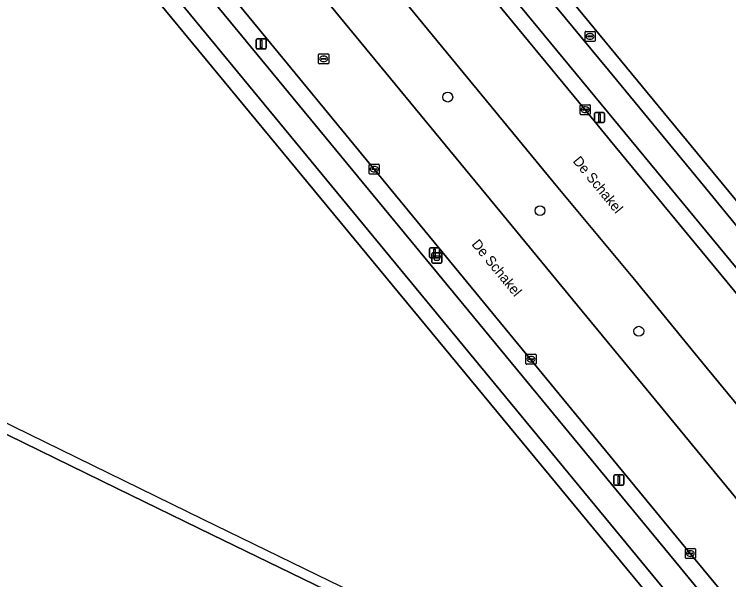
# Model space of a CAD drawing. Extents: x 156141 to 158132, y 385651 to 388333.
# Drawn here: x 156871.2 to 156942.3, y 386572.8 to 386629.1 of the extents above; entities that cross this region are included whole.
import ezdxf

# ---------------------------------------------------------------- set-up
doc = ezdxf.new("R2010")
doc.units = 0
for name, color, linetype in [('IMGEO_Afvalbak', 7, 'Continuous'), ('IMGEO_Berm_groen', 7, 'Continuous'), ('IMGEO_Boom', 7, 'Continuous'), ('IMGEO_Brandkraan', 7, 'Continuous'), ('IMGEO_Erf', 7, 'Continuous'), ('IMGEO_Fietspad_gesloten', 7, 'Continuous'), ('IMGEO_Kolk', 7, 'Continuous'), ('IMGEO_Lichtmast', 7, 'Continuous'), ('IMGEO_Openbare_ruimte_label', 7, 'Continuous'), ('IMGEO_Pand', 7, 'Continuous'), ('IMGEO_Pand_overbouw', 7, 'Continuous'), ('IMGEO_Rijbaan_lokaal_gesloten', 7, 'Continuous'), ('IMGEO_Rioolput', 7, 'Continuous'), ('IMGEO_Voetpad_open', 7, 'Continuous')]:
    doc.layers.add(name, color=color, linetype=linetype)

msp = doc.modelspace()

# ---------------------------------------------------------------- linework, layer by layer
at = {"layer": 'IMGEO_Afvalbak'}
for p, q in [((156912.79, 386604.402), (156912.79, 386605.202)), ((156912.79, 386605.202), (156912.79, 386604.402)), ((156912.89, 386605.302), (156913.68, 386605.302)), ((156913.68, 386605.302), (156912.89, 386605.302)), ((156913.78, 386605.202), (156913.78, 386604.402)), ((156913.78, 386604.402), (156913.78, 386605.202)), ((156913.68, 386604.302), (156912.89, 386604.302)), ((156912.89, 386604.302), (156913.68, 386604.302))]:
    msp.add_line(p, q, dxfattribs=at)
msp.add_lwpolyline([(156912.933, 386605.016), (156913.637, 386605.016), (156913.488, 386604.546), (156913.082, 386604.546), (156912.933, 386605.016)], dxfattribs=at)
for centre, start, end in [((156912.89, 386605.202), 90, 180), ((156912.89, 386605.202), 90, 180), ((156913.68, 386605.202), 0, 90), ((156913.68, 386605.202), 360, 90), ((156912.89, 386604.402), 180, 270), ((156912.89, 386604.402), 180, 270), ((156913.68, 386604.402), 270, 0), ((156913.68, 386604.402), 270, 0)]:
    msp.add_arc(centre, 0.1, start, end, dxfattribs=at)
at = {"layer": 'IMGEO_Berm_groen'}
for points in [[(156873.15, 386675.263), (156864.415, 386685.927), (156859.757, 386682.162), (156868.582, 386671.357), (156906.633, 386625.114), (156920.647, 386608.134), (156928.199, 386598.947), (156933.331, 386592.718), (156946.242, 386577.021)], [(156950.773, 386580.924), (156939.278, 386594.885), (156932.934, 386602.652), (156925.322, 386611.835), (156873.15, 386675.263)]]:
    msp.add_lwpolyline(points, dxfattribs=at)
for points in [[(156853.684, 386678.56), (156851.061, 386678.853), (156937.507, 386573.955), (156942.955, 386567.338), (156954.381, 386553.461), (156961.988, 386544.223), (156981.707, 386520.274), (156981.808, 386520.357), (156981.886, 386522.718), (156969.993, 386537.173), (156967.693, 386539.965), (156963.321, 386545.249), (156955.673, 386554.535), (156954.392, 386556.062), (156950.447, 386560.886), (156944.252, 386568.405), (156938.824, 386574.994)], [(156919.722, 386632.162), (156919.107, 386630.378), (156928.03, 386619.562), (156930.553, 386616.467), (156936.959, 386608.687), (156942.149, 386602.405), (156957.953, 386583.151), (156959.211, 386584.266)]]:
    msp.add_lwpolyline(points, close=True, dxfattribs=at)
at = {"layer": 'IMGEO_Boom'}
for centre in [(156914.365, 386620.818), (156923.54, 386609.516), (156933.37, 386597.512)]:
    msp.add_circle(centre, 0.489, dxfattribs=at)
at = {"layer": 'IMGEO_Brandkraan'}
for p, q in [((156928.021, 386626.433), (156928.021, 386627.285)), ((156928.096, 386627.359), (156928.948, 386627.359)), ((156928.28, 386626.853), (156928.28, 386626.865)), ((156928.718, 386626.816), (156928.32, 386626.816)), ((156928.323, 386626.902), (156928.721, 386626.902)), ((156928.509, 386627.139), (156928.534, 386627.139)), ((156928.764, 386626.865), (156928.764, 386626.853)), ((156929.022, 386627.285), (156929.022, 386626.433)), ((156928.948, 386626.359), (156928.096, 386626.359)), ((156928.532, 386626.579), (156928.507, 386626.579))]:
    msp.add_line(p, q, dxfattribs=at)
for points in [[(156928.021, 386626.433), (156928.021, 386627.285)], [(156928.096, 386627.359), (156928.948, 386627.359)], [(156929.022, 386627.285), (156929.022, 386626.433)], [(156928.948, 386626.359), (156928.096, 386626.359)]]:
    msp.add_lwpolyline(points, dxfattribs=at)
for centre, radius, start, end in [((156928.098, 386627.283), 0.0765, 91.55205, 178.44795), ((156928.098, 386627.283), 0.0765, 91.55205, 178.44795), ((156928.32, 386626.862), 0.0403, 85.87752, 175.75265), ((156928.317, 386626.852), 0.0366, 178.93798, 274.71019), ((156928.721, 386626.859), 0.043, 264.86636, 352.45326), ((156928.725, 386626.864), 0.0386, 1.73085, 96.63898), ((156928.946, 386627.283), 0.0765, 1.55205, 88.44795), ((156928.946, 386627.283), 0.0765, 1.55205, 88.44795), ((156928.098, 386626.435), 0.0765, 181.55205, 268.44795), ((156928.098, 386626.435), 0.0765, 181.55205, 268.44795), ((156928.946, 386626.435), 0.0765, 271.55205, 358.44795), ((156928.946, 386626.435), 0.0765, 271.55205, 358.44795)]:
    msp.add_arc(centre, radius, start, end, dxfattribs=at)
for centre, major_axis, ratio, start_param, end_param in [((156928.508, 386626.859), (-0.387, 0.002), 0.722429, 4.712389, 7.853982), ((156928.533, 386626.859), (-0.39, 0.002), 0.717154, 1.570796, 4.712389)]:
    msp.add_ellipse(centre, major_axis=major_axis, ratio=ratio, start_param=start_param, end_param=end_param, dxfattribs=at)
at = {"layer": 'IMGEO_Erf'}
for points in [[(156934.051, 386571.56), (156837.85, 386688.098)], [(156920.91, 386652.293), (156913.636, 386646.333), (156919.699, 386638.931), (156919.907, 386638.664), (156922.955, 386634.963), (156962.332, 386587.153), (156969.416, 386578.552), (156982.109, 386563.141), (156988.377, 386555.544), (157000, 386541.408), (157034.096, 386500), (157043.743, 386488.284), (157044.247, 386487.672), (157048.737, 386482.212), (157049.528, 386481.275), (157107.842, 386410.438)], [(156755.29, 386532.425), (156793.031, 386609.781), (156801.988, 386605.403), (156806.261, 386614.168), (156807.998, 386617.732), (156811.03, 386616.252), (156823.398, 386610.216), (156827.159, 386608.38), (156847.15, 386598.623), (156847.581, 386599.51), (156847.347, 386599.625), (156848.727, 386602.442), (156858.425, 386597.691), (156857.311, 386595.418), (156857.047, 386594.879), (156856.838, 386594.981), (156856.403, 386594.106), (156864.434, 386590.186), (156881.483, 386581.864), (156890.863, 386577.289), (156902.199, 386571.759)]]:
    msp.add_lwpolyline(points, dxfattribs=at)
at = {"layer": 'IMGEO_Fietspad_gesloten'}
msp.add_lwpolyline([(156851.061, 386678.853), (156847.15, 386683.599), (156841.168, 386690.858), (156839.176, 386689.202), (156935.219, 386572.64), (156940.947, 386565.685), (156947.362, 386557.896), (156952.399, 386551.77), (156960.01, 386542.525), (156964.129, 386537.511), (156979.696, 386518.607), (156981.707, 386520.274), (156961.988, 386544.223), (156954.381, 386553.461), (156942.955, 386567.338), (156937.507, 386573.955)], close=True, dxfattribs=at)
msp.add_lwpolyline([(156980.814, 386562.193), (156968.169, 386577.52), (156962.991, 386583.796), (156962.975, 386583.816), (156961.077, 386586.126), (156945.221, 386605.421), (156940.42, 386611.244), (156933.921, 386619.151), (156931.133, 386622.526), (156921.719, 386633.951), (156918.661, 386637.662), (156914.78, 386642.408), (156912.82, 386644.789), (156910.836, 386643.079), (156915.158, 386637.822), (156916.43, 386636.155), (156919.722, 386632.162), (156959.211, 386584.266), (156960.954, 386582.152), (156961.009, 386582.085), (156966.266, 386575.7), (156977.384, 386562.197)], dxfattribs=at)
at = {"layer": 'IMGEO_Kolk'}
for p, q in [((156927.534, 386619.137), (156927.534, 386619.989)), ((156927.609, 386620.063), (156928.461, 386620.063)), ((156928.022, 386619.843), (156928.047, 386619.843)), ((156928.535, 386619.989), (156928.535, 386619.137)), ((156928.461, 386619.063), (156927.609, 386619.063)), ((156927.793, 386619.557), (156927.793, 386619.569)), ((156928.231, 386619.52), (156927.833, 386619.52)), ((156927.836, 386619.606), (156928.234, 386619.606)), ((156928.045, 386619.283), (156928.02, 386619.283)), ((156928.277, 386619.569), (156928.277, 386619.557)), ((156906.544, 386613.218), (156906.544, 386614.07)), ((156906.619, 386614.144), (156907.471, 386614.144)), ((156907.545, 386614.07), (156907.545, 386613.218)), ((156906.803, 386613.638), (156906.803, 386613.65)), ((156907.241, 386613.601), (156906.843, 386613.601)), ((156906.846, 386613.687), (156907.244, 386613.687)), ((156907.055, 386613.364), (156907.03, 386613.364)), ((156907.032, 386613.924), (156907.057, 386613.924)), ((156907.287, 386613.65), (156907.287, 386613.638)), ((156907.471, 386613.144), (156906.619, 386613.144)), ((156922.143, 386594.3), (156922.143, 386595.152)), ((156922.218, 386595.226), (156923.07, 386595.226)), ((156922.445, 386594.769), (156922.843, 386594.769)), ((156922.631, 386595.006), (156922.656, 386595.006)), ((156923.144, 386595.152), (156923.144, 386594.3)), ((156923.07, 386594.226), (156922.218, 386594.226)), ((156922.402, 386594.72), (156922.402, 386594.732)), ((156922.84, 386594.683), (156922.442, 386594.683)), ((156922.654, 386594.446), (156922.629, 386594.446)), ((156922.886, 386594.732), (156922.886, 386594.72)), ((156937.996, 386574.956), (156937.996, 386575.808)), ((156938.071, 386575.882), (156938.923, 386575.882)), ((156938.484, 386575.662), (156938.509, 386575.662)), ((156938.997, 386575.808), (156938.997, 386574.956)), ((156938.923, 386574.882), (156938.071, 386574.882)), ((156938.255, 386575.376), (156938.255, 386575.388)), ((156938.693, 386575.339), (156938.295, 386575.339)), ((156938.298, 386575.425), (156938.696, 386575.425)), ((156938.507, 386575.102), (156938.482, 386575.102)), ((156938.739, 386575.388), (156938.739, 386575.376))]:
    msp.add_line(p, q, dxfattribs=at)
for points in [[(156927.534, 386619.137), (156927.534, 386619.989)], [(156927.609, 386620.063), (156928.461, 386620.063)], [(156928.535, 386619.989), (156928.535, 386619.137)], [(156928.461, 386619.063), (156927.609, 386619.063)], [(156906.544, 386613.218), (156906.544, 386614.07)], [(156906.619, 386614.144), (156907.471, 386614.144)], [(156907.545, 386614.07), (156907.545, 386613.218)], [(156907.471, 386613.144), (156906.619, 386613.144)], [(156922.143, 386594.3), (156922.143, 386595.152)], [(156922.218, 386595.226), (156923.07, 386595.226)], [(156923.144, 386595.152), (156923.144, 386594.3)], [(156923.07, 386594.226), (156922.218, 386594.226)], [(156937.996, 386574.956), (156937.996, 386575.808)], [(156938.071, 386575.882), (156938.923, 386575.882)], [(156938.997, 386575.808), (156938.997, 386574.956)], [(156938.923, 386574.882), (156938.071, 386574.882)]]:
    msp.add_lwpolyline(points, dxfattribs=at)
for centre, radius, start, end in [((156927.611, 386619.987), 0.0765, 91.55205, 178.44795), ((156927.611, 386619.987), 0.0765, 91.55205, 178.44795), ((156928.459, 386619.987), 0.0765, 1.55205, 88.44795), ((156928.459, 386619.987), 0.0765, 1.55205, 88.44795), ((156927.611, 386619.139), 0.0765, 181.55205, 268.44795), ((156927.611, 386619.139), 0.0765, 181.55205, 268.44795), ((156927.833, 386619.566), 0.0403, 85.87752, 175.75265), ((156927.83, 386619.556), 0.0366, 178.93798, 274.71019), ((156928.234, 386619.563), 0.043, 264.86636, 352.45326), ((156928.238, 386619.568), 0.0386, 1.73085, 96.63898), ((156928.459, 386619.139), 0.0765, 271.55205, 358.44795), ((156928.459, 386619.139), 0.0765, 271.55205, 358.44795), ((156906.621, 386614.068), 0.0765, 91.55205, 178.44795), ((156906.621, 386614.068), 0.0765, 91.55205, 178.44795), ((156907.469, 386614.068), 0.0765, 1.55205, 88.44795), ((156907.469, 386614.068), 0.0765, 1.55205, 88.44795), ((156906.843, 386613.647), 0.0403, 85.87752, 175.75265), ((156906.84, 386613.637), 0.0366, 178.93798, 274.71019), ((156907.244, 386613.644), 0.043, 264.86636, 352.45326), ((156907.248, 386613.649), 0.0386, 1.73085, 96.63898), ((156906.621, 386613.22), 0.0765, 181.55205, 268.44795), ((156906.621, 386613.22), 0.0765, 181.55205, 268.44795), ((156907.469, 386613.22), 0.0765, 271.55205, 358.44795), ((156907.469, 386613.22), 0.0765, 271.55205, 358.44795), ((156922.22, 386595.15), 0.0765, 91.55205, 178.44795), ((156922.22, 386595.15), 0.0765, 91.55205, 178.44795), ((156922.442, 386594.729), 0.0403, 85.87752, 175.75265), ((156922.847, 386594.731), 0.0386, 1.73085, 96.63898), ((156923.068, 386595.15), 0.0765, 1.55205, 88.44795), ((156923.068, 386595.15), 0.0765, 1.55205, 88.44795), ((156922.22, 386594.302), 0.0765, 181.55205, 268.44795), ((156922.22, 386594.302), 0.0765, 181.55205, 268.44795), ((156922.439, 386594.719), 0.0366, 178.93798, 274.71019), ((156922.843, 386594.726), 0.043, 264.86636, 352.45326), ((156923.068, 386594.302), 0.0765, 271.55205, 358.44795), ((156923.068, 386594.302), 0.0765, 271.55205, 358.44795), ((156938.073, 386575.806), 0.0765, 91.55205, 178.44795), ((156938.073, 386575.806), 0.0765, 91.55205, 178.44795), ((156938.921, 386575.806), 0.0765, 1.55205, 88.44795), ((156938.921, 386575.806), 0.0765, 1.55205, 88.44795), ((156938.073, 386574.958), 0.0765, 181.55205, 268.44795), ((156938.073, 386574.958), 0.0765, 181.55205, 268.44795), ((156938.295, 386575.385), 0.0403, 85.87752, 175.75265), ((156938.292, 386575.375), 0.0366, 178.93798, 274.71019), ((156938.696, 386575.382), 0.043, 264.86636, 352.45326), ((156938.7, 386575.387), 0.0386, 1.73085, 96.63898), ((156938.921, 386574.958), 0.0765, 271.55205, 358.44795), ((156938.921, 386574.958), 0.0765, 271.55205, 358.44795)]:
    msp.add_arc(centre, radius, start, end, dxfattribs=at)
for centre, major_axis, ratio, start_param, end_param in [((156928.021, 386619.563), (-0.387, 0.002), 0.722429, 4.712389, 7.853982), ((156928.046, 386619.563), (-0.39, 0.002), 0.717154, 1.570796, 4.712389), ((156907.031, 386613.644), (-0.387, 0.002), 0.722429, 4.712389, 7.853982), ((156907.056, 386613.644), (-0.39, 0.002), 0.717154, 1.570796, 4.712389), ((156922.63, 386594.726), (-0.387, 0.002), 0.722429, 4.712389, 7.853982), ((156922.655, 386594.726), (-0.39, 0.002), 0.717154, 1.570796, 4.712389), ((156938.483, 386575.382), (-0.387, 0.002), 0.722429, 4.712389, 7.853982), ((156938.508, 386575.382), (-0.39, 0.002), 0.717154, 1.570796, 4.712389)]:
    msp.add_ellipse(centre, major_axis=major_axis, ratio=ratio, start_param=start_param, end_param=end_param, dxfattribs=at)
at = {"layer": 'IMGEO_Lichtmast'}
for p, q in [((156895.3, 386625.707), (156895.3, 386626.507)), ((156895.3, 386626.507), (156895.3, 386625.707)), ((156895.4, 386626.607), (156896.19, 386626.607)), ((156896.19, 386626.607), (156895.4, 386626.607)), ((156896.29, 386626.507), (156896.29, 386625.707)), ((156896.29, 386625.707), (156896.29, 386626.507)), ((156896.19, 386625.607), (156895.4, 386625.607)), ((156895.4, 386625.607), (156896.19, 386625.607)), ((156928.968, 386618.379), (156928.968, 386619.179)), ((156928.968, 386619.179), (156928.968, 386618.379)), ((156929.068, 386619.279), (156929.858, 386619.279)), ((156929.858, 386619.279), (156929.068, 386619.279)), ((156929.958, 386619.179), (156929.958, 386618.379)), ((156929.958, 386618.379), (156929.958, 386619.179)), ((156929.858, 386618.279), (156929.068, 386618.279)), ((156929.068, 386618.279), (156929.858, 386618.279)), ((156912.548, 386604.905), (156912.548, 386605.705)), ((156912.548, 386605.705), (156912.548, 386604.905)), ((156912.648, 386605.805), (156913.438, 386605.805)), ((156913.438, 386605.805), (156912.648, 386605.805)), ((156913.538, 386605.705), (156913.538, 386604.905)), ((156913.538, 386604.905), (156913.538, 386605.705)), ((156913.438, 386604.805), (156912.648, 386604.805)), ((156912.648, 386604.805), (156913.438, 386604.805)), ((156930.88, 386582.302), (156930.88, 386583.102)), ((156930.88, 386583.102), (156930.88, 386582.302)), ((156930.98, 386583.202), (156931.77, 386583.202)), ((156931.77, 386583.202), (156930.98, 386583.202)), ((156931.87, 386583.102), (156931.87, 386582.302)), ((156931.87, 386582.302), (156931.87, 386583.102)), ((156931.77, 386582.202), (156930.98, 386582.202)), ((156930.98, 386582.202), (156931.77, 386582.202))]:
    msp.add_line(p, q, dxfattribs=at)
for points in [[(156895.72, 386626.482), (156895.87, 386626.482), (156895.87, 386625.732), (156895.72, 386625.732), (156895.72, 386626.482)], [(156929.388, 386619.154), (156929.538, 386619.154), (156929.538, 386618.404), (156929.388, 386618.404), (156929.388, 386619.154)], [(156912.968, 386605.68), (156913.118, 386605.68), (156913.118, 386604.93), (156912.968, 386604.93), (156912.968, 386605.68)], [(156931.3, 386583.077), (156931.45, 386583.077), (156931.45, 386582.327), (156931.3, 386582.327), (156931.3, 386583.077)]]:
    msp.add_lwpolyline(points, dxfattribs=at)
for centre, start, end in [((156895.4, 386626.507), 90, 180), ((156895.4, 386626.507), 90, 180), ((156896.19, 386626.507), 0, 90), ((156896.19, 386626.507), 360, 90), ((156895.4, 386625.707), 180, 270), ((156895.4, 386625.707), 180, 270), ((156896.19, 386625.707), 270, 0), ((156896.19, 386625.707), 270, 0), ((156929.068, 386619.179), 90, 180), ((156929.068, 386619.179), 90, 180), ((156929.858, 386619.179), 0, 90), ((156929.858, 386619.179), 360, 90), ((156929.068, 386618.379), 180, 270), ((156929.068, 386618.379), 180, 270), ((156929.858, 386618.379), 270, 0), ((156929.858, 386618.379), 270, 0), ((156912.648, 386605.705), 90, 180), ((156912.648, 386605.705), 90, 180), ((156913.438, 386605.705), 0, 90), ((156913.438, 386605.705), 360, 90), ((156912.648, 386604.905), 180, 270), ((156912.648, 386604.905), 180, 270), ((156913.438, 386604.905), 270, 0), ((156913.438, 386604.905), 270, 0), ((156930.98, 386583.102), 90, 180), ((156930.98, 386583.102), 90, 180), ((156931.77, 386583.102), 0, 90), ((156931.77, 386583.102), 360, 90), ((156930.98, 386582.302), 180, 270), ((156930.98, 386582.302), 180, 270), ((156931.77, 386582.302), 270, 0), ((156931.77, 386582.302), 270, 0)]:
    msp.add_arc(centre, 0.1, start, end, dxfattribs=at)
at = {"layer": 'IMGEO_Pand'}
msp.add_lwpolyline([(156941.806, 386537.182), (156921.589, 386547.043), (156915.658, 386549.938), (156914.031, 386550.732), (156915.273, 386553.271), (156914.594, 386553.611), (156913.349, 386551.065), (156905.925, 386554.687), (156907.174, 386557.24), (156906.492, 386557.574), (156905.242, 386555.021), (156896.189, 386559.439), (156902.199, 386571.759), (156890.863, 386577.289), (156881.483, 386581.864), (156864.434, 386590.186), (156856.403, 386594.106), (156854.672, 386594.951)], dxfattribs=at)
at = {"layer": 'IMGEO_Pand_overbouw'}
msp.add_lwpolyline([(156857.047, 386594.879), (156856.838, 386594.981), (156856.403, 386594.106), (156864.434, 386590.186), (156881.483, 386581.864), (156890.863, 386577.289), (156902.199, 386571.759), (156896.189, 386559.439), (156905.242, 386555.021), (156905.925, 386554.687), (156913.349, 386551.065), (156914.031, 386550.732), (156915.658, 386549.938), (156922.1, 386563.132), (156906.611, 386570.688), (156906.512, 386570.736), (156904.8, 386571.572), (156904.701, 386571.62), (156902.625, 386572.633), (156890.02, 386578.781), (156864.863, 386591.064)], close=True, dxfattribs=at)
at = {"layer": 'IMGEO_Rijbaan_lokaal_gesloten'}
for points in [[(156993.399, 386540.123), (156989.447, 386544.942), (156984.318, 386551.234), (156984.225, 386551.348), (156977.682, 386559.245), (156976.151, 386561.124), (156975.956, 386561.363), (156968.937, 386569.872), (156968.003, 386570.938), (156964.951, 386574.644), (156959.652, 386581.081), (156957.953, 386583.151), (156942.149, 386602.405), (156936.959, 386608.687), (156930.553, 386616.467), (156928.03, 386619.562), (156919.107, 386630.378), (156914.518, 386635.94), (156913.916, 386636.651), (156911.362, 386639.806), (156909.53, 386641.997), (156903.832, 386648.955), (156899.018, 386654.793), (156855.441, 386707.704)], [(156840.884, 386694.139), (156843.409, 386691.026), (156843.564, 386690.837), (156844.157, 386690.118), (156847.426, 386686.171), (156847.51, 386686.07), (156853.684, 386678.56), (156938.824, 386574.994), (156944.252, 386568.405), (156950.447, 386560.886), (156954.392, 386556.062), (156955.673, 386554.535), (156963.321, 386545.249), (156967.693, 386539.965), (156969.993, 386537.173), (156981.886, 386522.718), (156985.569, 386518.241), (156993.209, 386508.961)], [(156864.299, 386686.069), (156864.415, 386685.927), (156873.15, 386675.263), (156925.322, 386611.835)], [(156981.07, 386534.737), (156980.74, 386535.11), (156978.915, 386537.31), (156975.907, 386540.965), (156974.678, 386542.474), (156959.168, 386561.302), (156959.04, 386561.457), (156955.457, 386565.816), (156954.918, 386566.472), (156949.664, 386572.86), (156946.242, 386577.021), (156933.331, 386592.718), (156928.199, 386598.947), (156920.647, 386608.134), (156906.633, 386625.114), (156868.582, 386671.357), (156859.757, 386682.162), (156859.731, 386682.194)], [(156925.322, 386611.835), (156932.934, 386602.652), (156939.278, 386594.885), (156950.773, 386580.924), (156954.282, 386576.66), (156959.708, 386570.066), (156960.113, 386569.576), (156963.775, 386565.144), (156979.293, 386546.275), (156984.332, 386540.154), (156985.138, 386539.199), (156985.652, 386538.581), (156985.788, 386538.408)]]:
    msp.add_lwpolyline(points, dxfattribs=at)
at = {"layer": 'IMGEO_Rioolput'}
for p, q in [((156901.517, 386624.199), (156901.517, 386625.051)), ((156901.592, 386625.125), (156902.444, 386625.125)), ((156901.776, 386624.619), (156901.776, 386624.631)), ((156901.819, 386624.668), (156902.217, 386624.668)), ((156902.005, 386624.905), (156902.03, 386624.905)), ((156902.26, 386624.631), (156902.26, 386624.619)), ((156902.518, 386625.051), (156902.518, 386624.199)), ((156902.444, 386624.125), (156901.592, 386624.125)), ((156902.214, 386624.582), (156901.816, 386624.582)), ((156902.028, 386624.345), (156902.003, 386624.345))]:
    msp.add_line(p, q, dxfattribs=at)
for points in [[(156901.517, 386624.199), (156901.517, 386625.051)], [(156901.592, 386625.125), (156902.444, 386625.125)], [(156902.518, 386625.051), (156902.518, 386624.199)], [(156902.444, 386624.125), (156901.592, 386624.125)]]:
    msp.add_lwpolyline(points, dxfattribs=at)
for centre, radius, start, end in [((156901.594, 386625.049), 0.0765, 91.55205, 178.44795), ((156901.594, 386625.049), 0.0765, 91.55205, 178.44795), ((156901.816, 386624.628), 0.0403, 85.87752, 175.75265), ((156901.813, 386624.618), 0.0366, 178.93798, 274.71019), ((156902.217, 386624.625), 0.043, 264.86636, 352.45326), ((156902.221, 386624.63), 0.0386, 1.73085, 96.63898), ((156902.442, 386625.049), 0.0765, 1.55205, 88.44795), ((156902.442, 386625.049), 0.0765, 1.55205, 88.44795), ((156901.594, 386624.201), 0.0765, 181.55205, 268.44795), ((156901.594, 386624.201), 0.0765, 181.55205, 268.44795), ((156902.442, 386624.201), 0.0765, 271.55205, 358.44795), ((156902.442, 386624.201), 0.0765, 271.55205, 358.44795)]:
    msp.add_arc(centre, radius, start, end, dxfattribs=at)
for centre, major_axis, ratio, start_param, end_param in [((156902.004, 386624.625), (-0.387, 0.002), 0.722429, 4.712389, 7.853982), ((156902.029, 386624.625), (-0.39, 0.002), 0.717154, 1.570796, 4.712389)]:
    msp.add_ellipse(centre, major_axis=major_axis, ratio=ratio, start_param=start_param, end_param=end_param, dxfattribs=at)
at = {"layer": 'IMGEO_Voetpad_open'}
for points in [[(156839.176, 386689.202), (156838.705, 386688.81), (156837.85, 386688.098), (156934.051, 386571.56), (156944.356, 386559.041), (156951.164, 386550.769), (156952.399, 386551.77), (156947.362, 386557.896), (156940.947, 386565.685), (156935.219, 386572.64)], [(156921.719, 386633.951), (156931.133, 386622.526), (156933.921, 386619.151), (156940.42, 386611.244), (156945.221, 386605.421), (156961.077, 386586.126), (156962.332, 386587.153), (156922.955, 386634.963)]]:
    msp.add_lwpolyline(points, close=True, dxfattribs=at)

# ---------------------------------------------------------------- texts
at = {"layer": 'IMGEO_Openbare_ruimte_label'}
for p in [(156926.751, 386614.421), (156916.68, 386606.148)]:
    msp.add_text('De Schakel', height=1, rotation=309.48286, dxfattribs=at).set_placement(p)

doc.saveas('drawing.dxf')
